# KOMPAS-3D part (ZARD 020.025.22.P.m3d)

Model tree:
1. Плоскость XY
2. Плоскость ZX
3. Плоскость ZY
4. Ось X
5. Ось Y
6. Ось Z
7. Начало координат
8. Булева операция:1
9. Булева операция:2
10. Булева операция:5
11. Булева операция:6
